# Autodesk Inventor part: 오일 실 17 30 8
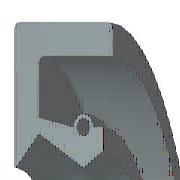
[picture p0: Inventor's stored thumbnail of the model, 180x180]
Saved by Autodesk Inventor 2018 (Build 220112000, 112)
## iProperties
IsCustomPart: 1
Created: 2012-02
Part Number: 오일 실 17 30 8
Material: 고무
Description: 오일-실
Document SubType Name: Modeling
Standard: KS B 2804
Designer: mduedu
Standards Organization: KS
Language: ko-KR
Size Designation: D - 17 30 8
Categories: <MemberInstance><Categories><Category DisplayName="샤프트 부품" InternalName="7f7aeb1f-a693-4053-b835-cee3144e0d98" Mnemonic="SHFT"><Category DisplayName="실링" Intern
Density: 0.93 g/cm^3
Appearance: 고무 - 검은색 - 버전 1.1
Author: mduedu
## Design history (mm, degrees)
revolve "본체" stored, may be unused: angle "d17" = 90 deg
revolve "스프링1" stored, may be unused: angle "d18" = 90 deg
body "Solid1"
sketch "스케치1"
  geometry: L1 (0, 15)-(8, 15); L2 (8, 13.25)-(1.75, 13.25); L3 (1.75, 10.25)-(4.9, 8.5); L4 (4.9, 8.5)-(0, 8.5); L5 (0, 0)-(9.586, 0) reference; L6 (4.9, 8.5)-(6.3, 9.375); L7 (0, 18)-(0, -3) reference; L8 (-1.941, 0)-(11.507, 0) reference; L9 (4.2, 10.6)-(1.75, 11.21); L10 (1.75, 11.21)-(1.75, 13.25); L11 (0, 15)-(0, 8.588); L12 (4.9, 8.5)-(0, 8.5); L13 (1.75, 10.25)-(0.152, 8.528); L14 (8, 15)-(8, 13.25); L15 (5.6, 10.6)-(6.3, 10.6); L16 (6.3, 10.6)-(6.3, 9.375); C1 r 0.455 at (4.9, 10.6); A1 r 0.7 centre (4.9, 10.6) between (5.6, 10.6) and (4.2, 10.6); A2 r 0.088 centre (0.088, 8.588) between (0, 8.588) and (0.152, 8.528); 1 further point
  constraints: 28 end point, 5 horizontal alignment, 5 point on line, 4 point on circle, 4 vertical alignment, 3 centre point, 3 tangent, 2 collinear, 2 horizontal, 2 perpendicular, 1 coincident, 1 parallel
  dimensions: "d0" = 30 diameter of L1 L5 (= SD2); "d1" = 1.75 distance of L1.end L2.start (= SD); "d2" = 0.91 diameter of C1 (= SPDI); "d3" = 1.4 diameter of A1 (= SPDA); "d4" = 17 diameter of L3.end L5 (= NND); "d5" = 20.5 diameter of L3.start L5 (= TKDM); "d7" = 22.42 diameter of L9.end L5 (= TKDM + 0.24 x SWDT); "d8" = 1.75 distance between parallel lines of L11 L10 (= SD); "d9" = 4.9 distance from line of L11 C1.centre (= SPDST); "d10" = 21.2 diameter of C1.centre L5 (= HLDM); "d11" = 0.0875 radius of A2 (= 0.25 x LAB); "d12" = 6.3 distance between parallel lines of L11 L16 (= SDI); "d13" = 18.75 diameter of L6.end L5 (= ABDM); "d14" = 8 distance from line of L11 L1.end (= SWDT)
fillet "모깎기1" dims "d6" = 0.3 (= RR)
other parameters: "SD2" = 30 [user parameter; used in 1 equation term], "SWDT" = 8 [user parameter; used in 2 equation terms], "RR" = 0.3 [user parameter; used in 1 equation term], "SD" = 1.75 [user parameter; used in 2 equation terms], "NND" = 17 [user parameter; used in 1 equation term], "SPDA" = 1.4 [user parameter; used in 1 equation term], "SPDI" = 0.91 [user parameter; used in 1 equation term], "TKDM" = 20.5 [user parameter; used in 2 equation terms], "HLDM" = 21.2 [user parameter; used in 1 equation term], "ABDM" = 18.75 [user parameter; used in 1 equation term], "SDI" = 6.3 [user parameter; used in 1 equation term], "SPDST" = 4.9 [user parameter; used in 1 equation term], "LAB" = 0.35 [user parameter; used in 1 equation term], "d15" = 0, "d16" = 0, "d19" = 0
